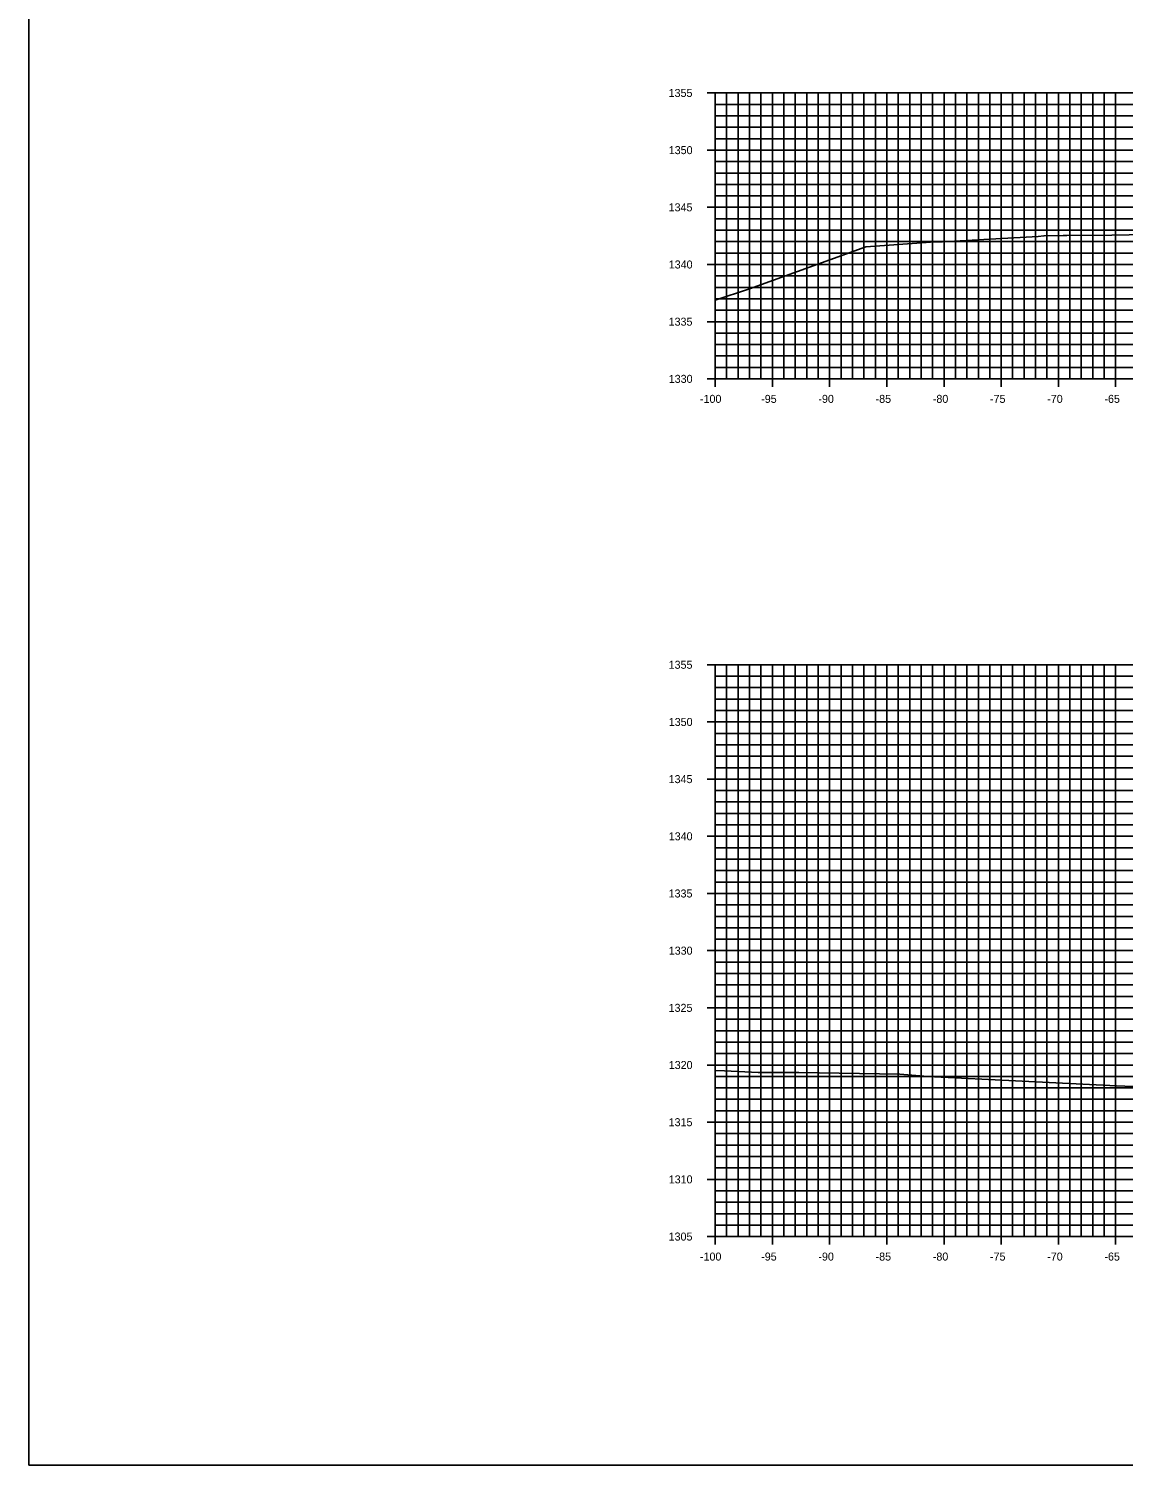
# Model space of a CAD drawing. Extents: x 674939 to 678919, y 750652 to 765176.
# Drawn here: x 678578.5 to 678674.2, y 752532.6 to 752658.2 of the extents above; entities that cross this region are included whole.
import ezdxf

# ---------------------------------------------------------------- set-up
doc = ezdxf.new("R2010")
doc.units = 0
for name, color, linetype in [('Level 10', 7, 'Continuous'), ('Level 20', 7, 'Continuous'), ('Level 4', 7, 'Continuous'), ('Level 8', 7, 'Continuous'), ('Level 9', 7, 'Continuous')]:
    doc.layers.add(name, color=color, linetype=linetype)

msp = doc.modelspace()

# ---------------------------------------------------------------- linework, layer by layer
at = {"layer": 'Level 10'}
for points in [[(678638.53, 752634.43), (678641.52, 752635.41), (678651.71, 752639.09), (678656.98, 752639.46), (678657.36, 752639.5), (678658.41, 752639.53), (678663.05, 752639.8), (678666.75, 752640.01), (678667.26, 752640.06), (678667.29, 752640.05), (678668.94, 752640.08), (678669.24, 752640.08), (678669.27, 752640.08), (678673.2, 752640.12), (678677.73, 752640.21)], [(678638.53, 752567.07), (678639.35, 752567.03), (678642.28, 752566.91), (678645.85, 752566.89), (678654.66, 752566.74), (678657.12, 752566.56), (678673.6, 752565.74), (678683.94, 752565.33), (678699.2, 752564.68), (678706.43, 752564.38), (678716.52, 752563.96), (678728.3, 752563.47), (678732.11, 752563.31), (678744.59, 752562.79), (678746.38, 752562.72), (678759.39, 752562.18), (678760.75, 752562.12), (678769.84, 752561.98)]]:
    msp.add_lwpolyline(points, dxfattribs=at)
at = {"layer": 'Level 20'}
for p, q in [((678638.53, 752652.55), (678838.53, 752652.55)), ((678638.53, 752627.55), (678638.53, 752652.55)), ((678638.53, 752651.55), (678838.53, 752651.55)), ((678639.53, 752627.55), (678639.53, 752652.55)), ((678640.53, 752627.55), (678640.53, 752652.55)), ((678641.53, 752627.55), (678641.53, 752652.55)), ((678642.53, 752627.55), (678642.53, 752652.55)), ((678643.53, 752627.55), (678643.53, 752652.55)), ((678644.53, 752627.55), (678644.53, 752652.55)), ((678645.53, 752627.55), (678645.53, 752652.55)), ((678646.53, 752627.55), (678646.53, 752652.55)), ((678647.53, 752627.55), (678647.53, 752652.55)), ((678648.53, 752627.55), (678648.53, 752652.55)), ((678649.53, 752627.55), (678649.53, 752652.55)), ((678650.53, 752627.55), (678650.53, 752652.55)), ((678651.53, 752627.55), (678651.53, 752652.55)), ((678652.53, 752627.55), (678652.53, 752652.55)), ((678653.53, 752627.55), (678653.53, 752652.55)), ((678654.53, 752627.55), (678654.53, 752652.55)), ((678655.53, 752627.55), (678655.53, 752652.55)), ((678656.53, 752627.55), (678656.53, 752652.55)), ((678657.53, 752627.55), (678657.53, 752652.55)), ((678658.53, 752627.55), (678658.53, 752652.55)), ((678659.53, 752627.55), (678659.53, 752652.55)), ((678660.53, 752627.55), (678660.53, 752652.55)), ((678661.53, 752627.55), (678661.53, 752652.55)), ((678662.53, 752627.55), (678662.53, 752652.55)), ((678663.53, 752627.55), (678663.53, 752652.55)), ((678664.53, 752627.55), (678664.53, 752652.55)), ((678665.53, 752627.55), (678665.53, 752652.55)), ((678666.53, 752627.55), (678666.53, 752652.55)), ((678667.53, 752627.55), (678667.53, 752652.55)), ((678668.53, 752627.55), (678668.53, 752652.55)), ((678669.53, 752627.55), (678669.53, 752652.55)), ((678670.53, 752627.55), (678670.53, 752652.55)), ((678671.53, 752627.55), (678671.53, 752652.55)), ((678672.53, 752627.55), (678672.53, 752652.55)), ((678673.53, 752627.55), (678673.53, 752652.55)), ((678638.53, 752650.55), (678838.53, 752650.55)), ((678638.53, 752649.55), (678838.53, 752649.55)), ((678638.53, 752648.55), (678838.53, 752648.55)), ((678638.53, 752647.55), (678838.53, 752647.55)), ((678638.53, 752646.55), (678838.53, 752646.55)), ((678638.53, 752645.55), (678838.53, 752645.55)), ((678638.53, 752644.55), (678838.53, 752644.55)), ((678638.53, 752643.55), (678838.53, 752643.55)), ((678638.53, 752642.55), (678838.53, 752642.55)), ((678638.53, 752641.55), (678838.53, 752641.55)), ((678638.53, 752640.55), (678838.53, 752640.55)), ((678638.53, 752639.55), (678838.53, 752639.55)), ((678638.53, 752638.55), (678838.53, 752638.55)), ((678638.53, 752637.55), (678838.53, 752637.55)), ((678638.53, 752636.55), (678838.53, 752636.55)), ((678638.53, 752635.55), (678838.53, 752635.55)), ((678638.53, 752634.55), (678838.53, 752634.55)), ((678638.53, 752633.55), (678838.53, 752633.55)), ((678638.53, 752632.55), (678838.53, 752632.55)), ((678638.53, 752631.55), (678838.53, 752631.55)), ((678638.53, 752630.55), (678838.53, 752630.55)), ((678638.53, 752629.55), (678838.53, 752629.55)), ((678638.53, 752628.55), (678838.53, 752628.55)), ((678638.53, 752627.55), (678838.53, 752627.55)), ((678638.53, 752602.55), (678838.53, 752602.55)), ((678638.53, 752552.55), (678638.53, 752602.55)), ((678639.53, 752552.55), (678639.53, 752602.55)), ((678640.53, 752552.55), (678640.53, 752602.55)), ((678641.53, 752552.55), (678641.53, 752602.55)), ((678642.53, 752552.55), (678642.53, 752602.55)), ((678643.53, 752552.55), (678643.53, 752602.55)), ((678644.53, 752552.55), (678644.53, 752602.55)), ((678645.53, 752552.55), (678645.53, 752602.55)), ((678646.53, 752552.55), (678646.53, 752602.55)), ((678647.53, 752552.55), (678647.53, 752602.55)), ((678648.53, 752552.55), (678648.53, 752602.55)), ((678649.53, 752552.55), (678649.53, 752602.55)), ((678650.53, 752552.55), (678650.53, 752602.55)), ((678651.53, 752552.55), (678651.53, 752602.55)), ((678652.53, 752552.55), (678652.53, 752602.55)), ((678653.53, 752552.55), (678653.53, 752602.55)), ((678654.53, 752552.55), (678654.53, 752602.55)), ((678655.53, 752552.55), (678655.53, 752602.55)), ((678656.53, 752552.55), (678656.53, 752602.55)), ((678657.53, 752552.55), (678657.53, 752602.55)), ((678658.53, 752552.55), (678658.53, 752602.55)), ((678659.53, 752552.55), (678659.53, 752602.55)), ((678660.53, 752552.55), (678660.53, 752602.55)), ((678661.53, 752552.55), (678661.53, 752602.55)), ((678662.53, 752552.55), (678662.53, 752602.55)), ((678663.53, 752552.55), (678663.53, 752602.55)), ((678664.53, 752552.55), (678664.53, 752602.55)), ((678665.53, 752552.55), (678665.53, 752602.55)), ((678666.53, 752552.55), (678666.53, 752602.55)), ((678667.53, 752552.55), (678667.53, 752602.55)), ((678668.53, 752552.55), (678668.53, 752602.55)), ((678669.53, 752552.55), (678669.53, 752602.55)), ((678670.53, 752552.55), (678670.53, 752602.55)), ((678671.53, 752552.55), (678671.53, 752602.55)), ((678672.53, 752552.55), (678672.53, 752602.55)), ((678673.53, 752552.55), (678673.53, 752602.55)), ((678638.53, 752601.55), (678838.53, 752601.55)), ((678638.53, 752600.55), (678838.53, 752600.55)), ((678638.53, 752599.55), (678838.53, 752599.55)), ((678638.53, 752598.55), (678838.53, 752598.55)), ((678638.53, 752597.55), (678838.53, 752597.55)), ((678638.53, 752596.55), (678838.53, 752596.55)), ((678638.53, 752595.55), (678838.53, 752595.55)), ((678638.53, 752594.55), (678838.53, 752594.55)), ((678638.53, 752593.55), (678838.53, 752593.55)), ((678638.53, 752592.55), (678838.53, 752592.55)), ((678638.53, 752591.55), (678838.53, 752591.55)), ((678638.53, 752590.55), (678838.53, 752590.55)), ((678638.53, 752589.55), (678838.53, 752589.55)), ((678638.53, 752588.55), (678838.53, 752588.55)), ((678638.53, 752587.55), (678838.53, 752587.55)), ((678638.53, 752586.55), (678838.53, 752586.55)), ((678638.53, 752585.55), (678838.53, 752585.55)), ((678638.53, 752584.55), (678838.53, 752584.55)), ((678638.53, 752583.55), (678838.53, 752583.55)), ((678638.53, 752582.55), (678838.53, 752582.55)), ((678638.53, 752581.55), (678838.53, 752581.55)), ((678638.53, 752580.55), (678838.53, 752580.55)), ((678638.53, 752579.55), (678838.53, 752579.55)), ((678638.53, 752578.55), (678838.53, 752578.55)), ((678638.53, 752577.55), (678838.53, 752577.55)), ((678638.53, 752576.55), (678838.53, 752576.55)), ((678638.53, 752575.55), (678838.53, 752575.55)), ((678638.53, 752574.55), (678838.53, 752574.55)), ((678638.53, 752573.55), (678838.53, 752573.55)), ((678638.53, 752572.55), (678838.53, 752572.55)), ((678638.53, 752571.55), (678838.53, 752571.55)), ((678638.53, 752570.55), (678838.53, 752570.55)), ((678638.53, 752569.55), (678838.53, 752569.55)), ((678638.53, 752568.55), (678838.53, 752568.55)), ((678638.53, 752567.55), (678838.53, 752567.55)), ((678638.53, 752566.55), (678838.53, 752566.55)), ((678638.53, 752565.55), (678838.53, 752565.55)), ((678638.53, 752564.55), (678838.53, 752564.55)), ((678638.53, 752563.55), (678838.53, 752563.55)), ((678638.53, 752562.55), (678838.53, 752562.55)), ((678638.53, 752561.55), (678838.53, 752561.55)), ((678638.53, 752560.55), (678838.53, 752560.55)), ((678638.53, 752559.55), (678838.53, 752559.55)), ((678638.53, 752558.55), (678838.53, 752558.55)), ((678638.53, 752557.55), (678838.53, 752557.55)), ((678638.53, 752556.55), (678838.53, 752556.55)), ((678638.53, 752555.55), (678838.53, 752555.55)), ((678638.53, 752554.55), (678838.53, 752554.55)), ((678638.53, 752553.55), (678838.53, 752553.55)), ((678638.53, 752552.55), (678838.53, 752552.55))]:
    msp.add_line(p, q, dxfattribs=at)
at = {"layer": 'Level 4'}
msp.add_lwpolyline([(678578.53, 752532.55), (678918.53, 752532.55), (678918.53, 752752.55), (678578.53, 752752.55)], close=True, dxfattribs=at)
at = {"layer": 'Level 8'}
for p, q in [((678637.83, 752652.55), (678639.23, 752652.55)), ((678638.53, 752627.55), (678638.53, 752652.55)), ((678638.53, 752651.55), (678638.88, 752651.55)), ((678638.53, 752650.55), (678638.88, 752650.55)), ((678638.53, 752649.55), (678638.88, 752649.55)), ((678638.53, 752648.55), (678638.88, 752648.55)), ((678637.83, 752647.55), (678639.23, 752647.55)), ((678638.53, 752646.55), (678638.88, 752646.55)), ((678638.53, 752645.55), (678638.88, 752645.55)), ((678638.53, 752644.55), (678638.88, 752644.55)), ((678638.53, 752643.55), (678638.88, 752643.55)), ((678637.83, 752642.55), (678639.23, 752642.55)), ((678638.53, 752641.55), (678638.88, 752641.55)), ((678638.53, 752640.55), (678638.88, 752640.55)), ((678638.53, 752639.55), (678638.88, 752639.55)), ((678638.53, 752638.55), (678638.88, 752638.55)), ((678637.83, 752637.55), (678639.23, 752637.55)), ((678638.53, 752636.55), (678638.88, 752636.55)), ((678638.53, 752635.55), (678638.88, 752635.55)), ((678638.53, 752634.55), (678638.88, 752634.55)), ((678637.83, 752632.55), (678639.23, 752632.55)), ((678638.53, 752633.55), (678638.88, 752633.55)), ((678638.53, 752631.55), (678638.88, 752631.55)), ((678638.53, 752630.55), (678638.88, 752630.55)), ((678638.53, 752629.55), (678638.88, 752629.55)), ((678637.83, 752627.55), (678639.23, 752627.55)), ((678638.53, 752628.55), (678638.88, 752628.55)), ((678638.53, 752626.85), (678638.53, 752628.25)), ((678638.53, 752627.55), (678838.53, 752627.55)), ((678643.53, 752626.85), (678643.53, 752628.25)), ((678648.53, 752626.85), (678648.53, 752628.25)), ((678653.53, 752626.85), (678653.53, 752628.25)), ((678658.53, 752626.85), (678658.53, 752628.25)), ((678663.53, 752626.85), (678663.53, 752628.25)), ((678668.53, 752626.85), (678668.53, 752628.25)), ((678673.53, 752626.85), (678673.53, 752628.25)), ((678637.83, 752602.55), (678639.23, 752602.55)), ((678638.53, 752552.55), (678638.53, 752602.55)), ((678638.53, 752601.55), (678638.88, 752601.55)), ((678638.53, 752600.55), (678638.88, 752600.55)), ((678638.53, 752599.55), (678638.88, 752599.55)), ((678637.83, 752597.55), (678639.23, 752597.55)), ((678638.53, 752598.55), (678638.88, 752598.55)), ((678638.53, 752596.55), (678638.88, 752596.55)), ((678638.53, 752595.55), (678638.88, 752595.55)), ((678638.53, 752594.55), (678638.88, 752594.55)), ((678637.83, 752592.55), (678639.23, 752592.55)), ((678638.53, 752593.55), (678638.88, 752593.55)), ((678638.53, 752591.55), (678638.88, 752591.55)), ((678638.53, 752590.55), (678638.88, 752590.55)), ((678638.53, 752589.55), (678638.88, 752589.55)), ((678637.83, 752587.55), (678639.23, 752587.55)), ((678638.53, 752588.55), (678638.88, 752588.55)), ((678638.53, 752586.55), (678638.88, 752586.55)), ((678638.53, 752585.55), (678638.88, 752585.55)), ((678638.53, 752584.55), (678638.88, 752584.55)), ((678638.53, 752583.55), (678638.88, 752583.55)), ((678637.83, 752582.55), (678639.23, 752582.55)), ((678638.53, 752581.55), (678638.88, 752581.55)), ((678638.53, 752580.55), (678638.88, 752580.55)), ((678638.53, 752579.55), (678638.88, 752579.55)), ((678638.53, 752578.55), (678638.88, 752578.55)), ((678637.83, 752577.55), (678639.23, 752577.55)), ((678638.53, 752576.55), (678638.88, 752576.55)), ((678638.53, 752575.55), (678638.88, 752575.55)), ((678638.53, 752574.55), (678638.88, 752574.55)), ((678638.53, 752573.55), (678638.88, 752573.55)), ((678637.83, 752572.55), (678639.23, 752572.55)), ((678638.53, 752571.55), (678638.88, 752571.55)), ((678638.53, 752570.55), (678638.88, 752570.55)), ((678638.53, 752569.55), (678638.88, 752569.55)), ((678638.53, 752568.55), (678638.88, 752568.55)), ((678637.83, 752567.55), (678639.23, 752567.55)), ((678638.53, 752566.55), (678638.88, 752566.55)), ((678638.53, 752565.55), (678638.88, 752565.55)), ((678638.53, 752564.55), (678638.88, 752564.55)), ((678638.53, 752563.55), (678638.88, 752563.55)), ((678637.83, 752562.55), (678639.23, 752562.55)), ((678638.53, 752561.55), (678638.88, 752561.55)), ((678638.53, 752560.55), (678638.88, 752560.55)), ((678638.53, 752559.55), (678638.88, 752559.55)), ((678638.53, 752558.55), (678638.88, 752558.55)), ((678637.83, 752557.55), (678639.23, 752557.55)), ((678638.53, 752556.55), (678638.88, 752556.55)), ((678638.53, 752555.55), (678638.88, 752555.55)), ((678638.53, 752554.55), (678638.88, 752554.55)), ((678638.53, 752553.55), (678638.88, 752553.55)), ((678637.83, 752552.55), (678639.23, 752552.55)), ((678638.53, 752551.85), (678638.53, 752553.25)), ((678638.53, 752552.55), (678838.53, 752552.55)), ((678643.53, 752551.85), (678643.53, 752553.25)), ((678648.53, 752551.85), (678648.53, 752553.25)), ((678653.53, 752551.85), (678653.53, 752553.25)), ((678658.53, 752551.85), (678658.53, 752553.25)), ((678663.53, 752551.85), (678663.53, 752553.25)), ((678668.53, 752551.85), (678668.53, 752553.25)), ((678673.53, 752551.85), (678673.53, 752553.25))]:
    msp.add_line(p, q, dxfattribs=at)

# ---------------------------------------------------------------- texts
at = {"layer": 'Level 9'}
for s, p in [('1355', (678634.46, 752652.2)), ('1350', (678634.47, 752647.2)), ('1345', (678634.46, 752642.2)), ('1340', (678634.47, 752637.2)), ('1335', (678634.46, 752632.2)), ('1330', (678634.47, 752627.2)), ('-100', (678637.2, 752625.45)), ('-95', (678642.55, 752625.45)), ('-90', (678647.55, 752625.45)), ('-85', (678652.55, 752625.45)), ('-80', (678657.55, 752625.45)), ('-75', (678662.55, 752625.45)), ('-70', (678667.55, 752625.45)), ('-65', (678672.55, 752625.45)), ('1355', (678634.46, 752602.2)), ('1350', (678634.47, 752597.2)), ('1345', (678634.46, 752592.2)), ('1340', (678634.47, 752587.2)), ('1335', (678634.46, 752582.2)), ('1330', (678634.47, 752577.2)), ('1325', (678634.46, 752572.2)), ('1320', (678634.47, 752567.2)), ('1315', (678634.46, 752562.2)), ('1310', (678634.47, 752557.2)), ('1305', (678634.46, 752552.2)), ('-100', (678637.2, 752550.45)), ('-95', (678642.55, 752550.45)), ('-90', (678647.55, 752550.45)), ('-85', (678652.55, 752550.45)), ('-80', (678657.55, 752550.45)), ('-75', (678662.55, 752550.45)), ('-70', (678667.55, 752550.45)), ('-65', (678672.55, 752550.45))]:
    msp.add_text(s, height=0.7, dxfattribs=at).set_placement(p)

doc.saveas('drawing.dxf')
